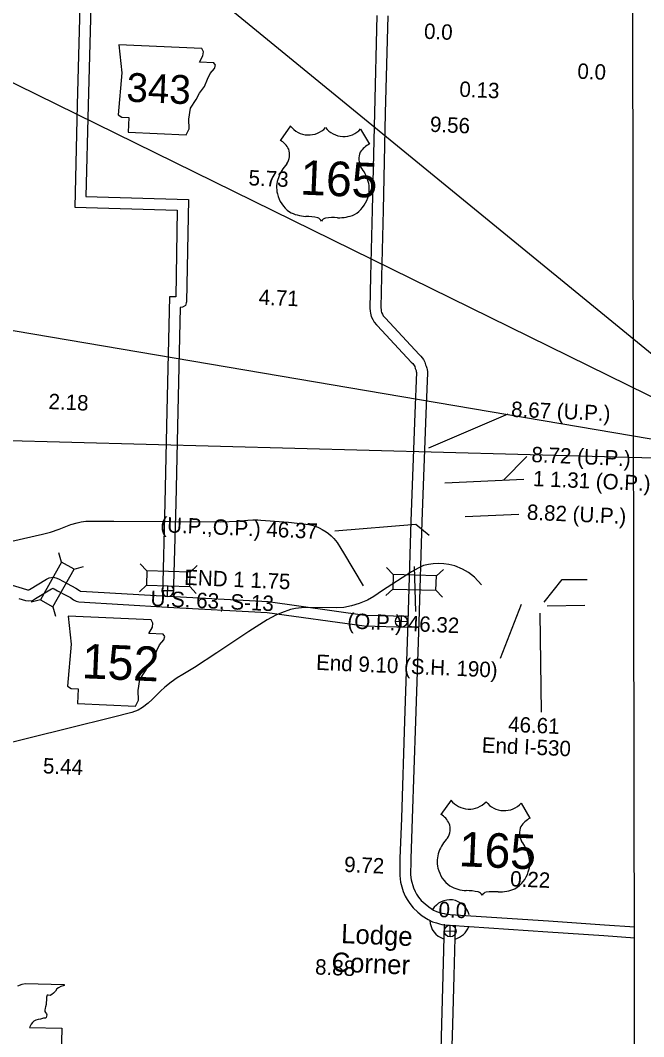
# Model space of a CAD drawing. Extents: x 1196286 to 1268366, y 2040822 to 2082115.
# Drawn here: x 1204184 to 1207611, y 2071244 to 2076830 of the extents above; entities that cross this region are included whole.
import ezdxf

# ---------------------------------------------------------------- set-up
doc = ezdxf.new("R2010")
doc.units = 0
for name, color, linetype in [('10', 7, 'Continuous'), ('Level 100', 7, 'Continuous'), ('Level 70', 7, 'Continuous'), ('Level 78', 7, 'Continuous'), ('Level 8', 7, 'Continuous'), ('Level 80', 7, 'Continuous'), ('Level 82', 7, 'Continuous'), ('Level 84', 7, 'Continuous'), ('Level 85', 7, 'Continuous'), ('Level 87', 7, 'Continuous'), ('Level 95', 7, 'Continuous'), ('Level 97', 7, 'Continuous'), ('Level 98', 7, 'Continuous')]:
    doc.layers.add(name, color=color, linetype=linetype)

msp = doc.modelspace()

# ---------------------------------------------------------------- linework, layer by layer
at = {"layer": '10'}
for points in [[(1204137.1, 2073967.3), (1204305.7, 2074005.9), (1204349.3, 2074017), (1204397.9, 2074033.5), (1204434.2, 2074048), (1204462.1, 2074058.3), (1204496.5, 2074067.9), (1204518.3, 2074072.9), (1204543.9, 2074076.3), (1204567.7, 2074077.5), (1204698, 2074077.5), (1205002.4, 2074074.4), (1205286.1, 2074074), (1205379.8, 2074076.7), (1205416.9, 2074081.7), (1205434.4, 2074082.8), (1205462, 2074084), (1205490.6, 2074083.6), (1205507.1, 2074083.2), (1205658.9, 2074071), (1205736.9, 2074063.3), (1205769.4, 2074058.3), (1205787.4, 2074054.9), (1205806.5, 2074048.8), (1205826.7, 2074040.4), (1205843.9, 2074032), (1205864.6, 2074019.3), (1205879.1, 2074009), (1205892.1, 2073997.1), (1205908.2, 2073981.1), (1205925.4, 2073959.6), (1205945.6, 2073927.5), (1205960, 2073903.7), (1206069, 2073722.6)], [(1206718.8, 2073727.6), (1206680.9, 2073769.6), (1206648.9, 2073794.7), (1206615.1, 2073813.5), (1206573.8, 2073831), (1206539.4, 2073839.8), (1206513.1, 2073843.5), (1206484.9, 2073844.2), (1206453.6, 2073842.9), (1206428.6, 2073839.8), (1206401, 2073832.9), (1206371.6, 2073819.7), (1206334.7, 2073797.8), (1206175, 2073695.7), (1206126.8, 2073662.5), (1206093, 2073643.1), (1206046.7, 2073624.3), (1206004.7, 2073611.1), (1205962.1, 2073603), (1205921.5, 2073599.9), (1205764.3, 2073602.4), (1205729.9, 2073601.1), (1205696.7, 2073598), (1205668.5, 2073591.7), (1205620.3, 2073573.6), (1205589, 2073560.4), (1205540.8, 2073534.7), (1205440.6, 2073470.2), (1205263.5, 2073353.7), (1205142, 2073273.5), (1205076.9, 2073235.3), (1205046.9, 2073216.5), (1205013, 2073192.7), (1204977.4, 2073164.5), (1204954.2, 2073143.2), (1204908.5, 2073096.2), (1204886, 2073076.2), (1204855.9, 2073053.6), (1204830.9, 2073038), (1204797.7, 2073026.1), (1204688.7, 2072998.5), (1204451.5, 2072939), (1204028.9, 2072835.7)]]:
    msp.add_lwpolyline(points, dxfattribs=at)
at = {"layer": 'Level 100'}
for p, q in [((1204993.7, 2073663.4), (1204994.9, 2073720.6)), ((1204961.8, 2073696.6), (1205026.9, 2073695.3)), ((1206278.3, 2073493.9), (1206279.6, 2073559)), ((1206246.4, 2073527.1), (1206311.5, 2073525.8)), ((1206546.8, 2071791.8), (1206548.1, 2071856.9)), ((1206514.9, 2071825), (1206580, 2071823.7))]:
    msp.add_line(p, q, dxfattribs=at)
for centre in [(1206278.9, 2073526.5), (1206547.5, 2071824.3)]:
    msp.add_circle(centre, 32.6, dxfattribs=at)
msp.add_arc((1204994.4, 2073696), 32.6, 139.0483, 41.9089, dxfattribs=at)
at = {"layer": 'Level 70'}
msp.add_lwpolyline([(1204170.2, 2071522.7), (1204194, 2071532.6), (1204209.5, 2071536.3), (1204424.5, 2071530.6), (1204425.1, 2071525.1), (1204407.1, 2071519.6), (1204394.3, 2071512.9), (1204385, 2071506.6), (1204377.1, 2071493.7), (1204366.6, 2071483.5), (1204356.4, 2071474.9), (1204347.7, 2071470.2), (1204337.5, 2071471.6), (1204332.1, 2071472.4), (1204326.9, 2071461.4), (1204327.5, 2071445.5), (1204326.1, 2071429.9), (1204325.4, 2071420.7), (1204321.8, 2071407.2), (1204320, 2071400.3), (1204318.6, 2071390.3), (1204318.7, 2071382.5), (1204322.2, 2071376.3), (1204328.4, 2071369.5), (1204329.2, 2071364.2), (1204327.3, 2071356.9), (1204325.4, 2071349.7), (1204321.7, 2071346.1), (1204311.6, 2071345.2), (1204293.9, 2071340.7), (1204282, 2071337.8), (1204268.4, 2071334.3), (1204257.7, 2071329.7), (1204250, 2071322), (1204243, 2071312.8), (1204238.2, 2071301.4), (1204234.1, 2071294.9), (1204412.1, 2071290.2), (1204398.6, 2070761.4)], dxfattribs=at)
at = {"layer": 'Level 78'}
for points in [[(1204725.7, 2076694.3), (1204742, 2076541.2), (1204722, 2076310.9), (1204741.8, 2076297.4), (1204779.8, 2076295.8), (1204776.3, 2076214.6), (1205095.8, 2076201), (1205112.4, 2076233.3), (1205109.6, 2076286.7), (1205119.8, 2076347.3), (1205149.8, 2076394.2), (1205169, 2076429), (1205196, 2076465.9), (1205213, 2076505.8), (1205227, 2076538.2), (1205251.1, 2076565.2), (1205256.9, 2076582.7), (1205247.3, 2076595.8), (1205168.7, 2076599.2), (1205188, 2076633.9), (1205191.5, 2076656.6), (1205181.7, 2076674.6)], [(1204447.5, 2073554.2), (1204463.8, 2073401.1), (1204443.8, 2073170.8), (1204463.5, 2073157.3), (1204501.5, 2073155.7), (1204498.1, 2073074.5), (1204817.5, 2073060.9), (1204834.1, 2073093.2), (1204831.4, 2073146.6), (1204841.6, 2073207.1), (1204871.5, 2073254.1), (1204890.8, 2073288.9), (1204917.8, 2073325.8), (1204934.7, 2073365.7), (1204948.8, 2073398.1), (1204972.8, 2073425.1), (1204978.6, 2073442.6), (1204969.1, 2073455.7), (1204890.5, 2073459.1), (1204909.7, 2073493.8), (1204913.2, 2073516.5), (1204903.5, 2073534.5)]]:
    msp.add_lwpolyline(points, close=True, dxfattribs=at)
at = {"layer": 'Level 8'}
for p in [(1204553.5, 2077535), (1203508.5, 2076797.1), (1200422, 2075757.5), (1199280.2, 2074652.1)]:
    msp.add_line(p, (1208376.7, 2074405.8), dxfattribs=at)
msp.add_lwpolyline([(1196285.8, 2082114.9), (1207540.7, 2082114.9), (1207563, 2069523.3), (1196285.8, 2069523.3)], close=True, dxfattribs=at)
at = {"layer": 'Level 80'}
for p, q in [((1205669, 2076249.1), (1205613.7, 2076171.1)), ((1206054.7, 2076232.5), (1206103.2, 2076150.1)), ((1206551.9, 2072543.7), (1206496.6, 2072465.7)), ((1206937.6, 2072527.2), (1206986, 2072444.8))]:
    msp.add_line(p, q, dxfattribs=at)
for centre, radius, start, end in [((1205769.1, 2076326.2), 126.4, 217.623, 317.2181), ((1205961.6, 2076318), 126.4, 217.8778, 317.4729), ((1205540.9, 2076057.5), 134.9, 28.3289, 57.5362), ((1205572.1, 2076091.8), 92.5, 326.3584, 18.7587), ((1206137.8, 2076067.5), 92.5, 156.3372, 208.7375), ((1206166, 2076030.7), 134.9, 117.5597, 146.767), ((1205805.6, 2075892), 215.7, 136.5044, 160.2393), ((1205888.1, 2075888.5), 215.7, 14.8566, 38.5915), ((1205735.2, 2075912.7), 142.6, 158.5056, 194.9298), ((1205960, 2075903.1), 142.6, 340.1661, 16.5903), ((1205758.4, 2075912.2), 165, 192.6554, 234.6791), ((1205936.9, 2075904.5), 165, 300.4168, 342.4405), ((1205763.7, 2075963.9), 211.8, 241.625, 267.1258), ((1205743, 2075364.5), 388, 78.7421, 88.5018), ((1205806.3, 2075710), 37.2, 25.5822, 70.5343), ((1205871.9, 2075707.2), 37.2, 104.5616, 149.5137), ((1205905.5, 2075357.6), 388, 86.5941, 96.3538), ((1205936, 2075956.5), 211.8, 267.9701, 293.4709), ((1206652, 2072620.9), 126.4, 217.623, 317.2181), ((1206844.5, 2072612.6), 126.4, 217.8778, 317.4729), ((1206423.8, 2072352.2), 134.9, 28.3289, 57.5362), ((1206455, 2072386.4), 92.5, 326.3584, 18.7587), ((1207048.8, 2072325.4), 134.9, 117.5597, 146.767), ((1207020.7, 2072362.2), 92.5, 156.3372, 208.7375), ((1206688.5, 2072186.7), 215.7, 136.5044, 160.2393), ((1206771, 2072183.2), 215.7, 14.8566, 38.5915), ((1206618.1, 2072207.4), 142.6, 158.5056, 194.9298), ((1206842.9, 2072197.8), 142.6, 340.1661, 16.5903), ((1206641.3, 2072206.8), 165, 192.6554, 234.6791), ((1206819.7, 2072199.2), 165, 300.4168, 342.4405), ((1206646.6, 2072258.6), 211.8, 241.625, 267.1258), ((1206625.8, 2071659.2), 388, 78.7421, 88.5018), ((1206689.2, 2072004.7), 37.2, 25.5822, 70.5343), ((1206754.7, 2072001.9), 37.2, 104.5616, 149.5137), ((1206788.3, 2071652.2), 388, 86.5941, 96.3538), ((1206818.9, 2072251.2), 211.8, 267.9701, 293.4709)]:
    msp.add_arc(centre, radius, start, end, dxfattribs=at)
at = {"layer": 'Level 82'}
for points in [[(1206429.5, 2074479.4), (1206865.7, 2074667.9)], [(1206839.9, 2074302.8), (1206968.6, 2074433.3)], [(1206518.3, 2074287.9), (1206952, 2074307.9)], [(1206629.8, 2074102.1), (1206925.8, 2074115.8)], [(1205913, 2074024.8), (1206357.7, 2074060.5), (1206432, 2073999.4)], [(1206357.7, 2073580.2), (1206350.9, 2073827.9)], [(1207064.8, 2073631.2), (1207163.5, 2073756.8), (1207299.9, 2073757)], [(1206824.5, 2073324.5), (1206939.7, 2073620.7)], [(1207080.1, 2073611.7), (1207287.8, 2073615.5)], [(1207049.8, 2073027.9), (1207042.9, 2073572.3)]]:
    msp.add_lwpolyline(points, dxfattribs=at)
at = {"layer": 'Level 84'}
for p, q in [((1206362, 2074895.3), (1206353.9, 2074669.8)), ((1206422, 2074893.1), (1206413.9, 2074667.6))]:
    msp.add_line(p, q, dxfattribs=at)
for points in [[(1206144.6, 2076856.6), (1206130.5, 2076321.7), (1206118.2, 2075787.8), (1206109.1, 2075422.1), (1206105.5, 2075247.7), (1206107.7, 2075230.5), (1206109.1, 2075220.8), (1206113.2, 2075201.8), (1206121.8, 2075186.3), (1206129.9, 2075170.9), (1206141.8, 2075157.1), (1206148, 2075150.9), (1206333.5, 2074951.5), (1206341.2, 2074943.5), (1206345.2, 2074938.8), (1206349.3, 2074932.9), (1206352.5, 2074927.5), (1206355.4, 2074916.5), (1206358.8, 2074909.3), (1206359.8, 2074905.1), (1206361.2, 2074898.4), (1206361.9, 2074894.8)], [(1206204.6, 2076855.2), (1206190.5, 2076320.2), (1206178.2, 2075786.3), (1206169.1, 2075420.7), (1206165.6, 2075251), (1206167.2, 2075238.5), (1206168.2, 2075231.3), (1206170, 2075223.2), (1206174.7, 2075214.7), (1206179.8, 2075204.9), (1206185.7, 2075198), (1206191.1, 2075192.7), (1206377.1, 2074992.7), (1206385.7, 2074983.8), (1206392.8, 2074975.4), (1206399.8, 2074965.3), (1206408.4, 2074950.7), (1206412, 2074937.1), (1206415.7, 2074929.3), (1206418.3, 2074918.4), (1206420, 2074910.6), (1206422.4, 2074898.5), (1206421.9, 2074892)], [(1206353.9, 2074669.8), (1206331.8, 2074076.5), (1206315, 2073524.1), (1206297, 2072979), (1206279, 2072444.6), (1206271.4, 2072223.2), (1206270.5, 2072184.2), (1206269.9, 2072162.8), (1206269.7, 2072129.2), (1206274.2, 2072092.9), (1206289.6, 2072041.5), (1206300.5, 2072016.7), (1206310.6, 2071997.2), (1206325.4, 2071975), (1206344.7, 2071951.5), (1206369.2, 2071928.4), (1206393.6, 2071908.1), (1206426.3, 2071887.2), (1206450.9, 2071875.7), (1206472.3, 2071869), (1206488.2, 2071864.8), (1206501.2, 2071861.2), (1206517.3, 2071858.6), (1206526.6, 2071856.8), (1206543.9, 2071856.1), (1207084.8, 2071820.2), (1207392.7, 2071799.1)], [(1206413.9, 2074667.6), (1206391.7, 2074074.5), (1206375, 2073522.2), (1206357, 2072977), (1206338.9, 2072442.6), (1206331.4, 2072221.5), (1206330.5, 2072182.7), (1206329.9, 2072161.7), (1206329.7, 2072132.7), (1206333.1, 2072105.3), (1206346, 2072062.2), (1206354.6, 2072042.6), (1206362.3, 2072027.7), (1206373.6, 2072010.8), (1206388.7, 2071992.5), (1206409, 2071973.3), (1206429.1, 2071956.6), (1206455.3, 2071939.9), (1206472.7, 2071931.8), (1206488.9, 2071926.7), (1206503.8, 2071922.8), (1206514.1, 2071919.9), (1206527.8, 2071917.7), (1206533.6, 2071916.6), (1206547, 2071916), (1207088.8, 2071880.1), (1207396.8, 2071859)], [(1207396.8, 2071859), (1207563, 2071847.8)], [(1207392.8, 2071799.1), (1207563, 2071787.7)]]:
    msp.add_lwpolyline(points, dxfattribs=at)
at = {"layer": 'Level 85'}
for start, end in [(14.5151, 149.4505), (182.186, 251.852), (285.4937, 340.5039)]:
    msp.add_arc((1206545.5, 2071886.1), 110, start, end, dxfattribs=at)
at = {"layer": 'Level 87'}
for points in [[(1206514.8, 2071861.3), (1206507, 2071579.9), (1206499.7, 2071312.3), (1206490, 2070957.9)], [(1206574.7, 2071856.2), (1206567, 2071578.2), (1206559.7, 2071310.6), (1206550, 2070956.3)]]:
    msp.add_lwpolyline(points, dxfattribs=at)
at = {"layer": 'Level 95'}
for points in [[(1204593, 2078107), (1204584.6, 2077570), (1204570.7, 2076906), (1204556.3, 2076363.1), (1204544.8, 2075860.8), (1205107.9, 2075845.4), (1205097.7, 2075281.9), (1205095.7, 2075276.4), (1205091.8, 2075262.6), (1205078.9, 2075255.9), (1205075.1, 2075253.8), (1205064.6, 2075250.9), (1205062.1, 2075251), (1205049.3, 2074679.6)], [(1204532.2, 2078054.2), (1204524.6, 2077571.1), (1204510.7, 2076907.4), (1204496.4, 2076364.6), (1204483.4, 2075802.5), (1205046.8, 2075787), (1205038.2, 2075311), (1205003.5, 2075310.7), (1204989.3, 2074680.9)], [(1204989.3, 2074680.8), (1204979, 2074177.1), (1204964.8, 2073667.8)], [(1205049.3, 2074679.6), (1205039, 2074175.6), (1205024.7, 2073664)], [(1204139.7, 2073725.1), (1204194, 2073709.3), (1204223.5, 2073699.6), (1204228.9, 2073699.3), (1204231.1, 2073699.6), (1204234.9, 2073702), (1204327.1, 2073758.7), (1204342.4, 2073765.6), (1204366.3, 2073769.3), (1204385.3, 2073764), (1204397.8, 2073757.8), (1204417.7, 2073746.7), (1204465.3, 2073721.6), (1204489.3, 2073709.4), (1204508.6, 2073696.5), (1204514.6, 2073693), (1204516.3, 2073692.6), (1204995.6, 2073664.3), (1205546.1, 2073634.7), (1206078.6, 2073561.4), (1206315.2, 2073554.1)], [(1204176.3, 2073651.9), (1204212.3, 2073640.2), (1204230.1, 2073639.2), (1204251.5, 2073641.3), (1204267, 2073651.3), (1204355.4, 2073705.6), (1204359.7, 2073707.5), (1204362.7, 2073708), (1204363.8, 2073707.7), (1204369.8, 2073704.7), (1204389, 2073693.9), (1204437.8, 2073668.3), (1204458.9, 2073657.6), (1204477, 2073645.4), (1204491.3, 2073637.2), (1204506.3, 2073633.1), (1204992.2, 2073604.4), (1205540.4, 2073574.9), (1206073.6, 2073501.6), (1206313.9, 2073494.1)]]:
    msp.add_lwpolyline(points, dxfattribs=at)
at = {"layer": 'Level 98'}
for p, q in [((1204410.4, 2073852.6), (1204396.1, 2073903.4)), ((1204479.5, 2073813.8), (1204530.3, 2073828.1)), ((1204879.8, 2073803.7), (1204843.5, 2073842)), ((1205117.3, 2073797), (1205155.7, 2073833.3)), ((1206234.1, 2073783.4), (1206197.9, 2073821.8)), ((1206471.6, 2073776.2), (1206510, 2073812.4)), ((1204877.6, 2073724.5), (1204839.2, 2073688.2)), ((1205115.1, 2073717.9), (1205151.4, 2073679.5)), ((1206231.7, 2073704.2), (1206193.2, 2073668)), ((1204294.1, 2073645.4), (1204243.3, 2073631.1)), ((1206469.2, 2073697), (1206505.3, 2073658.6)), ((1204363.2, 2073606.6), (1204377.5, 2073555.8))]:
    msp.add_line(p, q, dxfattribs=at)
for points in [[(1204363.2, 2073606.6), (1204479.5, 2073813.8), (1204410.4, 2073852.6), (1204294.1, 2073645.4)], [(1205117.3, 2073797), (1204879.8, 2073803.7), (1204877.6, 2073724.5), (1205115.1, 2073717.9)], [(1206471.6, 2073776.2), (1206234.1, 2073783.4), (1206231.7, 2073704.2), (1206469.2, 2073697)]]:
    msp.add_lwpolyline(points, close=True, dxfattribs=at)

# ---------------------------------------------------------------- texts
at = {"layer": 'Level 78'}
for s, height, p in [('343', 158.4, (1204764.8, 2076383.4)), ('152', 190.08, (1204519.6, 2073214.3))]:
    msp.add_text(s, height=height, rotation=357.548, dxfattribs=at).set_placement(p)
at = {"layer": 'Level 80'}
for p in [(1205720.2, 2075872.6), (1206592, 2072181.2)]:
    msp.add_text('165', height=190.08, rotation=357.548, dxfattribs=at).set_placement(p)
at = {"layer": 'Level 82'}
for s, p in [('0.13', (1206596.7, 2076410.1)), ('5.73', (1205437.3, 2075923)), ('4.71', (1205493.2, 2075267.4)), ('2.18', (1204337.2, 2074693.7)), ('5.44', (1204306.9, 2072691.3)), ('9.72', (1205963.1, 2072149.2)), ('0.22', (1206875.9, 2072070.5)), ('8.88', (1205803.2, 2071586.1))]:
    msp.add_text(s, height=84.48, rotation=357.548, dxfattribs=at).set_placement(p)
at = {"layer": 'Level 85'}
for s, p in [('Lodge ', (1205946.3, 2071758.4)), ('Corner', (1205893.2, 2071602.7))]:
    msp.add_text(s, height=105.6, rotation=357.548, dxfattribs=at).set_placement(p)
at = {"layer": 'Level 97'}
for s, p in [('0.0', (1206402.3, 2076728.6)), ('0.0', (1207245.5, 2076509.3)), ('9.56', (1206434.9, 2076217.2)), ('8.67 (U.P.)', (1206881.1, 2074650.8)), ('8.72 (U.P.)', (1206992.9, 2074402.1)), ('1 1.31 (O.P.)', (1207001.4, 2074270.2)), ('8.82 (U.P.)', (1206968, 2074085.3)), ('(U.P.,O.P.) 46.37', (1204952.1, 2074016.8)), ('END 1 1.75', (1205083.4, 2073727.5)), ('U.S. 63, S-13', (1204898.4, 2073611.4)), ('(O.P.) 46.32', (1205980.8, 2073487.6)), ('End 9.10 (S.H. 190)', (1205808.8, 2073260.1)), ('46.61', (1206864.8, 2072919.4)), ('End I-530', (1206720, 2072805.4)), ('0.0', (1206481.9, 2071901.3))]:
    msp.add_text(s, height=84.48, rotation=357.548, dxfattribs=at).set_placement(p)

doc.saveas('drawing.dxf')
